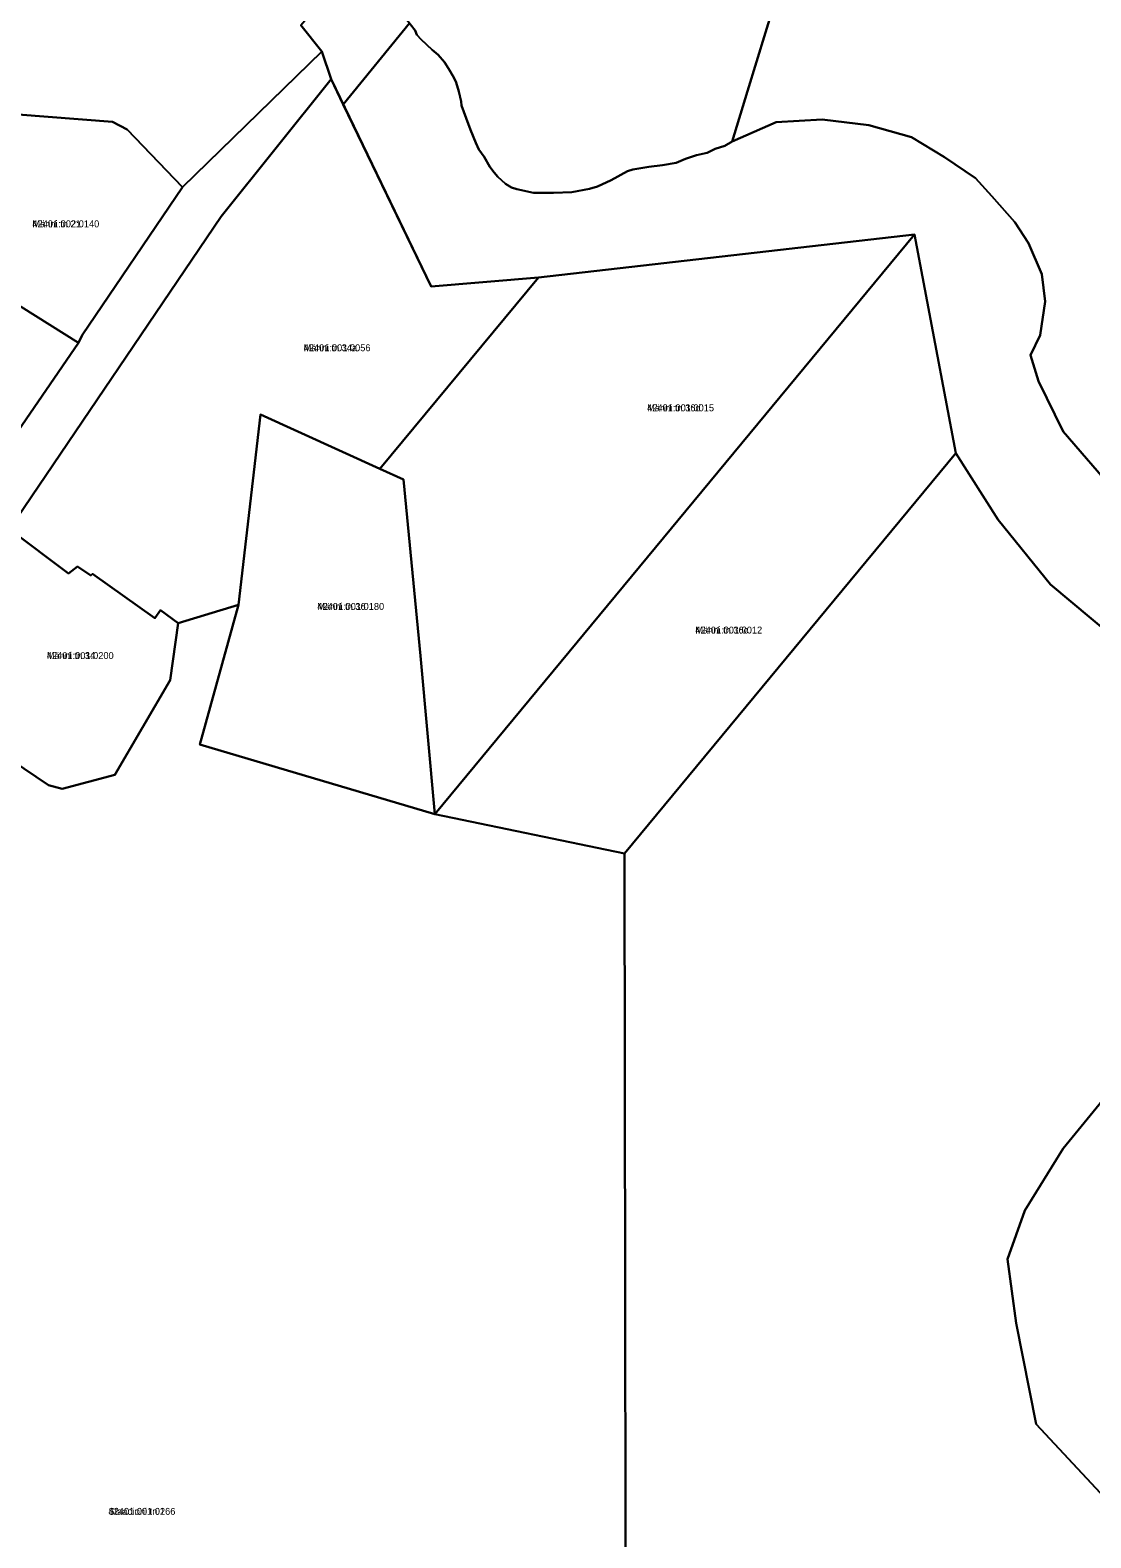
# Model space of a CAD drawing. Extents: x 595979 to 597983, y 6604231 to 6607350.
# Drawn here: x 597024.3 to 597254.4, y 6605722.5 to 6606049.7 of the extents above; entities that cross this region are included whole.
import ezdxf

# ---------------------------------------------------------------- set-up
doc = ezdxf.new("R2010")
doc.units = 0
for name, color, linetype in [('L_AADRESS', 7, 'Continuous'), ('PIIR', 7, 'Continuous'), ('TUNNUS', 7, 'Continuous')]:
    doc.layers.add(name, color=color, linetype=linetype)

msp = doc.modelspace()

# ---------------------------------------------------------------- linework, layer by layer
at = {"layer": 'PIIR'}
for points in [[(597083.05, 6606050.71), (597087.59, 6606045.02), (597057.4, 6606015.57), (597045.35, 6606028.13), (597042.19, 6606029.76), (597014.23, 6606031.96), (596997.32, 6606005.56), (596975.98, 6605972.14), (596955.37, 6605940.6), (596956.04, 6605934.38), (596951.35, 6605927.69), (596664.52, 6605976.79), (596695.91, 6606173.63)], [(597185.75, 6606055.52), (597179.95, 6606036.42), (597176.62, 6606025.47), (597175, 6606024.56), (597172.9, 6606023.91), (597171.16, 6606023.02), (597168.87, 6606022.54), (597166.5, 6606021.73), (597164.48, 6606020.85), (597161.5, 6606020.34), (597158.49, 6606019.98), (597155.03, 6606019.42), (597153.89, 6606019.03), (597150.34, 6606017.13), (597147.39, 6606015.76), (597145.63, 6606015.22), (597141.79, 6606014.49), (597137.83, 6606014.32), (597133.54, 6606014.32), (597129.89, 6606015.12), (597128.72, 6606015.54), (597127.47, 6606016.27), (597125.78, 6606017.83), (597124.97, 6606018.74), (597124.07, 6606019.99), (597122.79, 6606022.14), (597121.68, 6606023.75), (597120.98, 6606025.19), (597119.83, 6606028.04), (597118.89, 6606030.53), (597117.9, 6606033.3), (597117.82, 6606034.17), (597117.3, 6606036.36), (597116.76, 6606038.31), (597116.25, 6606039.37), (597115.11, 6606041.32), (597114.21, 6606042.71), (597112.85, 6606044.33), (597111.52, 6606045.35), (597109.11, 6606047.62), (597108.23, 6606048.6), (597107.82, 6606049.61), (597106.24, 6606051.6)], [(597259.9, 6605949.24), (597248.42, 6605962.57), (597243.04, 6605973.51), (597241.33, 6605979.14), (597243.4, 6605983.49), (597244.51, 6605990.75), (597243.74, 6605996.74), (597240.86, 6606003.4), (597237.93, 6606007.98), (597232.93, 6606013.63), (597229.35, 6606017.52), (597222.65, 6606022.1), (597215.52, 6606026.45), (597206.22, 6606029.05), (597196.08, 6606030.28), (597186.16, 6606029.7), (597176.62, 6606025.47), (597179.95, 6606036.42), (597185.75, 6606055.52)], [(597258.88, 6605918.33), (597245.66, 6605929.36), (597234.32, 6605943.41), (597225.11, 6605957.9), (597216.11, 6606005.31), (597134.57, 6605996), (597111.34, 6605994), (597092.26, 6606033.51), (597106.61, 6606051.14), (597107.82, 6606049.61), (597108.23, 6606048.6), (597109.11, 6606047.62), (597111.52, 6606045.35), (597112.85, 6606044.33), (597114.21, 6606042.71), (597115.11, 6606041.32), (597116.25, 6606039.37), (597116.76, 6606038.31), (597117.3, 6606036.36), (597117.82, 6606034.17), (597117.9, 6606033.3), (597118.89, 6606030.53), (597119.83, 6606028.04), (597120.98, 6606025.19), (597121.68, 6606023.75), (597122.79, 6606022.14), (597124.07, 6606019.99), (597124.97, 6606018.74), (597125.78, 6606017.83), (597127.47, 6606016.27), (597128.72, 6606015.54), (597129.89, 6606015.12), (597133.54, 6606014.32), (597137.83, 6606014.32), (597141.79, 6606014.49), (597145.63, 6606015.22), (597147.39, 6606015.76), (597150.34, 6606017.13), (597153.89, 6606019.03), (597155.03, 6606019.42), (597158.49, 6606019.98), (597161.5, 6606020.34), (597164.48, 6606020.85), (597166.5, 6606021.73), (597168.87, 6606022.54), (597171.16, 6606023.02), (597172.9, 6606023.91), (597175, 6606024.56), (597176.62, 6606025.47), (597186.16, 6606029.7), (597196.08, 6606030.28), (597206.22, 6606029.05), (597215.52, 6606026.45), (597222.65, 6606022.1), (597229.35, 6606017.52), (597232.93, 6606013.63), (597237.93, 6606007.98), (597240.86, 6606003.4), (597243.74, 6605996.74), (597244.51, 6605990.75), (597243.4, 6605983.49), (597241.33, 6605979.14), (597243.04, 6605973.51), (597248.42, 6605962.57), (597259.9, 6605949.24)], [(597011.15, 6605947.31), (597034.82, 6605981.8), (597035.59, 6605983.48), (597057.4, 6606015.57), (597087.59, 6606045.02), (597089.62, 6606038.98), (597065.74, 6606009.24), (597019.89, 6605941.36)], [(597254.66, 6605493.15), (597249.71, 6605498.34), (597237.59, 6605519.02), (597205.75, 6605555.84), (597198.31, 6605578.46), (597192.52, 6605576.03), (597186.73, 6605621.73), (597153.6, 6605628.55), (597153.23, 6605871.03), (597225.11, 6605957.9), (597234.32, 6605943.41), (597245.66, 6605929.36), (597258.88, 6605918.33)], [(597004.6, 6605901.84), (597028.34, 6605885.84), (597031.31, 6605885.03), (597042.72, 6605888.08), (597054.7, 6605908.63), (597056.42, 6605921), (597069.54, 6605924.99), (597061.14, 6605894.65), (597112.11, 6605879.53), (597153.23, 6605871.03), (597153.6, 6605628.55), (597146.78, 6605599.1), (597136.13, 6605552), (597133.33, 6605530.05), (597119.25, 6605542.22), (597124.12, 6605576.98), (597128.37, 6605607.35), (597089.46, 6605612.62), (597087.2, 6605596.63), (597053.54, 6605601.01), (597061.85, 6605657.99), (597070.41, 6605657.66), (597072.09, 6605693.55), (597015.38, 6605695.99)], [(597258.81, 6605819.74), (597248.39, 6605807), (597240.06, 6605793.55), (597236.33, 6605782.97), (597238.16, 6605769.1), (597242.56, 6605747.16), (597261.46, 6605726.85)], [(597261.46, 6605726.85), (597242.56, 6605747.16), (597238.16, 6605769.1), (597236.33, 6605782.97), (597240.06, 6605793.55), (597248.39, 6605807), (597258.81, 6605819.74)]]:
    msp.add_lwpolyline(points, dxfattribs=at)
for points in [[(597092.26, 6606033.51), (597089.62, 6606038.98), (597087.59, 6606045.02), (597083.05, 6606050.71), (597105.86, 6606077.47), (597131.85, 6606106.28), (597164.82, 6606146.62), (597177.93, 6606140.7), (597151.41, 6606109.53), (597124.7, 6606078.28), (597104.42, 6606054.65), (597106.24, 6606051.6), (597106.61, 6606051.14)], [(597032.68, 6605931.79), (597019.89, 6605941.36), (597065.74, 6606009.24), (597089.62, 6606038.98), (597111.34, 6605994), (597134.57, 6605996), (597100.21, 6605954.46), (597074.28, 6605966.24), (597069.54, 6605924.99), (597056.42, 6605921), (597052.59, 6605923.77), (597051.39, 6605922.09), (597037.84, 6605931.7), (597037.49, 6605931.33), (597034.59, 6605933.31)], [(597034.82, 6605981.8), (597013, 6605995.46), (597009.37, 6605997.72), (596997.32, 6606005.56), (597014.23, 6606031.96), (597042.19, 6606029.76), (597045.35, 6606028.13), (597057.4, 6606015.57), (597035.59, 6605983.48)], [(596975.98, 6605972.14), (596997.32, 6606005.56), (597009.37, 6605997.72), (597013, 6605995.46), (597034.82, 6605981.8), (597011.15, 6605947.31), (596990.71, 6605961.58), (596985.38, 6605965.43)], [(597134.57, 6605996), (597216.11, 6606005.31), (597112.11, 6605879.53), (597108.98, 6605913.92), (597105.29, 6605952.14), (597100.21, 6605954.46)], [(597216.11, 6606005.31), (597225.11, 6605957.9), (597153.23, 6605871.03), (597112.11, 6605879.53)], [(597105.29, 6605952.14), (597108.98, 6605913.92), (597112.11, 6605879.53), (597061.14, 6605894.65), (597069.54, 6605924.99), (597074.28, 6605966.24), (597100.21, 6605954.46)], [(597019.89, 6605941.36), (597032.68, 6605931.79), (597034.59, 6605933.31), (597037.49, 6605931.33), (597037.84, 6605931.7), (597051.39, 6605922.09), (597052.59, 6605923.77), (597056.42, 6605921), (597054.7, 6605908.63), (597042.72, 6605888.08), (597031.31, 6605885.03), (597028.34, 6605885.84), (597004.6, 6605901.84), (596999.66, 6605905.3), (596997.87, 6605909.24)]]:
    msp.add_lwpolyline(points, close=True, dxfattribs=at)

# ---------------------------------------------------------------- texts
at = {"layer": 'L_AADRESS'}
for s, p in [('Männi tn 21', (597024.83, 6606006.88)), ('Männi tn 34a', (597083.66, 6605979.99)), ('Männi tn 36d', (597158.16, 6605966.96)), ('Männi tn 36', (597086.62, 6605923.86)), ('Männi tn 36c', (597168.61, 6605918.74)), ('Männi tn 34', (597027.96, 6605913.2)), ('Staadioni tn 2', (597041.34, 6605727.52))]:
    msp.add_text(s, height=1.5, dxfattribs=at).set_placement(p)
at = {"layer": 'TUNNUS'}
for s, p in [('42401:002:0140', (597024.83, 6606006.88)), ('42401:001:0056', (597083.66, 6605979.99)), ('42401:001:0015', (597158.16, 6605966.96)), ('42401:001:0180', (597086.62, 6605923.86)), ('42401:001:0012', (597168.61, 6605918.74)), ('42401:001:0200', (597027.96, 6605913.2)), ('42401:001:0166', (597041.34, 6605727.52))]:
    msp.add_text(s, height=1.5, dxfattribs=at).set_placement(p)

doc.saveas('drawing.dxf')
